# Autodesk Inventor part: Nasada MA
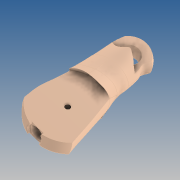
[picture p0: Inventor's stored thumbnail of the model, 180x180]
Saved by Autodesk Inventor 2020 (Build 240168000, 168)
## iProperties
Created: 2019-10
Part Number: Nasada MA
Material: GFRP
Document SubType Name: Modeling
Designer: yello
Density: 1.75 g/cm^3
Appearance: Default
Author: yello
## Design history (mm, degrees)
feature "Nasada MA"
workplane "Work Plane1"
sketch "Sketch2"
  geometry: L1 (-3.5, 0)-(-3.5, -20); L2 (-3.5, -20)-(3.5, -20); L3 (3.5, -20)-(3.5, 0); L4 (3.5, 0)-(3.5, 30); L5 (3.5, 30)-(-3.5, 30); L6 (-3.5, 30)-(-3.5, 0); L7 (0, 30)-(0, -20); L8 (0, 8.502)-(0, 11.113) reference; A1 r 3.5 centre (0, 0) between (-3.5, 0) and (3.5, 0)
  constraints: 16 end point, 3 perpendicular, 2 midpoint, 2 point on circle, 2 point on line, 2 tangent, 1 centre point, 1 collinear, 1 vertical, 2 other
  dimensions: "d1" = 7 diameter of A1; "d2" = 20 distance of L1.start L1.end; "d3" = 30 distance of L3.end L4.end
revolve "Revolution1" sketch "Sketch2" stored, may be unused: angle "d4" = 90 deg
workplane "Work Plane2"
sketch "Sketch3"
  geometry: C1 r 4.25 at (0, 0)
  constraints: 1 centre point
  dimensions: "d6" = 8.5 diameter of C1
extrude "Extrusion1" cut sketch "Sketch3" distance "d7" = 1.75; taper "d8" = 0 deg
workplane "Work Plane3"
sketch "Sketch4" dims "d11" = 3
  geometry: L1 (-3.403, 29.08)-(-11.266, 0.129); L2 (-11.266, 0.129)-(-11.66, -1.318); L3 (-0.025, 28.163)-(-6.78, 29.998) reference; 2 further points
  constraints: 4 end point, 1 coincident, 3 other
  dimensions: "d22" = 30 distance from line of L3 L2.start
revolve "Revolution2" sketch "Sketch4" stored, may be unused: angle "d12" = 90 deg
mirror "Mirror2"
workplane "Work Plane4"
sketch "Sketch7"
  geometry: L1 (-10, 3.5)-(-6.25, 3.5); L2 (-6.25, 3.5)-(2, 3.5); L3 (-6.25, 2.5)-(2, 2.5); L4 (2, 4.5)-(-6.25, 4.5); L5 (-10, 7)-(-10, 0) reference; A1 r 1 centre (-6.25, 3.5) between (-6.25, 4.5) and (-6.25, 2.5); A2 r 1 centre (2, 3.5) between (2, 2.5) and (2, 4.5); 1 further point
  constraints: 10 end point, 4 point on circle, 4 tangent, 2 centre point, 2 horizontal, 1 midpoint, 1 parallel
  dimensions: "d16" = 3.75 distance of L1.start L1.end; "d17" = 8.25 distance of L1.end L2.end; "d18" = 2 diameter of A2; "d23" = 0 distance from line of L5 L1.start
extrude "Extrusion3" cut sketch "Sketch7" distance "d19" = 3453; taper "d20" = 0 deg
fillet "Fillet1" dims "d21" = 1
sketch "Sketch8"
  geometry: C1 r 5 at (0, 0); 1 further point
  constraints: 1 centre point
  dimensions: "d24" = 10 diameter of C1
extrude "Extrusion4" cut sketch "Sketch8" distance "d25" = 8; taper "d26" = 0 deg
body "Solid1"
other parameters: "d5" = 38, "d9" = -0.5
